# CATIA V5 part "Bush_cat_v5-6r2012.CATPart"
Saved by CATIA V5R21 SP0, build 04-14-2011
Part number: Bush
Bounding box of the stored display mesh (mm): x 75 to 115, y 10 to 50, z 160 to 210
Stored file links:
  D:\CATIA V5R21 E-RESOURCES\CATIA-V5R21\catia-v5r21-Tut\c12-catia-v5r21-tut\c12-catia-v5r21-tut02\Bush_cat_v5r21.CATPart
  D:\CATIA V5R21 E-RESOURCES\CATIA-V5R21\catia-v5r21-Tut\c12-catia-v5r21-tut\c12-catia-v5r21-tut02\Assembly.CATProduct
  D:\CATIA V5R21 E-RESOURCES\CATIA-V5R21\catia-v5r21-Tut\c12-catia-v5r21-tut\c12-catia-v5r21-tut02\Guide Pillar.CATPart
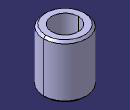
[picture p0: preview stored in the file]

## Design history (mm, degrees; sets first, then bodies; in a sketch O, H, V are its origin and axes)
Set1
  DatumSurface1: linked copy from another document
  DatumCurve1: linked copy from another document
Body1 (main body)
  Sketch1 on face of DatumSurface1, origin (0, 0, 200), H (1, 0, 0), V (0, 1, 0)
    projected circle E1 centre (95, 30) radius 12.5 from edge of DatumCurve1
    circle A1 centre (95, 30) radius 20
    point P1 (95, 30)
    radius A1 = 20
    concentricity: P1 E1, A1 E1
  Pad1: profile Sketch1, direction (0, 0, 1), length 10, opposite side length 40
  Chamfer1: length 2, angle 45, on face of Pad1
